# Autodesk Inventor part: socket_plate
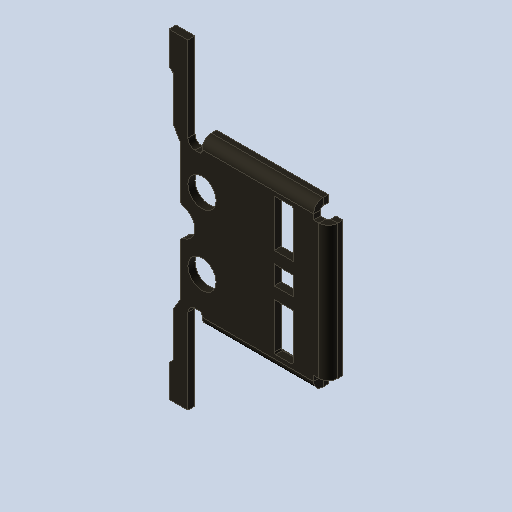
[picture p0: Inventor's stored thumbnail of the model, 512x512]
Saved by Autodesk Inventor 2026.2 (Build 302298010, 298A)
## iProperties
Created: 2026-10
Part Number: socket_plate
Material: Générique
Document SubType Name: Modeling
Designer: mel
Density: 1 g/cm^3
Appearance: Par défaut
Author: mel
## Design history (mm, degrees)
feature "Base1"
node "Solide1"
